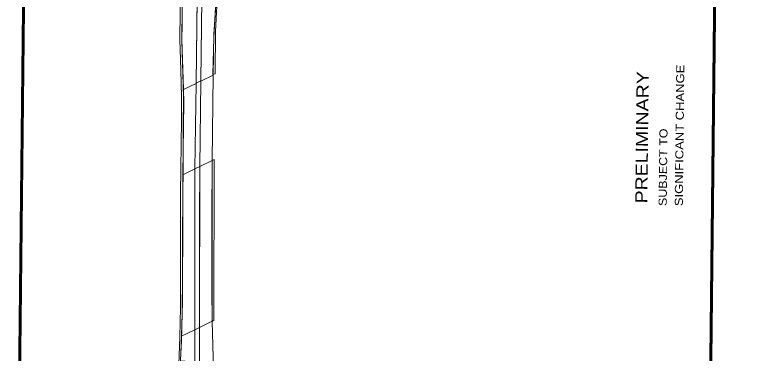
# Model space of a CAD drawing. Extents: x 2356576 to 2377878, y 6966390 to 6990634.
# Drawn here: x 2363518 to 2367164, y 6970821 to 6972488 of the extents above; entities that cross this region are included whole.
import ezdxf

# ---------------------------------------------------------------- set-up
doc = ezdxf.new("R2010")
doc.units = 0
doc.header["$LTSCALE"] = 7.1
for name, color, linetype, lineweight in [('10', 7, 'Continuous', 13), ('19', 7, 'Continuous', 13), ('8', 7, 'Continuous', 13)]:
    doc.layers.add(name, color=color, linetype=linetype, lineweight=lineweight)
doc.layers.add('5', color=7, linetype='Continuous')

msp = doc.modelspace()

# ---------------------------------------------------------------- linework, layer by layer
at = {"layer": '10'}
for points in [[(2364411.941, 6972150.306), (2364435.761, 6972161.792), (2364450.304, 6973379.724), (2364474.942, 6975290.834), (2364449.44, 6975291.283), (2364448.401, 6975249.217)], [(2364349.233, 6972119.087), (2364342.384, 6972367.508), (2364346.948, 6972816.216), (2364349.097, 6973027.453), (2364349.668, 6973070.227), (2364350.06, 6973172.738), (2364347.129, 6973327.684), (2364365.225, 6973327.282), (2364368.545, 6973567.259), (2364428.54, 6973566.551), (2364423.313, 6973123.743), (2364411.617, 6972149.404)], [(2364435.436, 6972160.979), (2364445.546, 6972973.819), (2364505.455, 6972965.741), (2364501.485, 6972629.356), (2364515.451, 6972628.365), (2364498.687, 6972392.189), (2364496.686, 6972190.744)], [(2364430.765, 6971740.43), (2364435.436, 6972160.979), (2364496.686, 6972190.744), (2364490.881, 6971769.645)], [(2364346.26, 6971699.083), (2364350.806, 6972057.614), (2364349.233, 6972119.087), (2364411.617, 6972149.404), (2364406.382, 6971728.861)], [(2364429.507, 6970948.178), (2364429.107, 6971490.067), (2364430.765, 6971740.43), (2364490.881, 6971769.645), (2364489.107, 6971490.18), (2364489.848, 6971133.24), (2364490.855, 6970978.883)], [(2364490.855, 6970978.883), (2364490.881, 6971769.645), (2364501.654, 6971775.019), (2364499.981, 6970983.653)], [(2364340.202, 6970904.333), (2364344.482, 6971073.663), (2364345.489, 6971289.033), (2364346.26, 6971699.083), (2364406.382, 6971728.861), (2364405.107, 6971490.021), (2364406.055, 6970936.781)], [(2364406.055, 6970936.781), (2364406.382, 6971728.861), (2364430.765, 6971740.43), (2364429.507, 6970948.178)], [(2364431.129, 6970286.36), (2364429.507, 6970948.178), (2364490.855, 6970978.883), (2364498.084, 6970741.164), (2364484.715, 6970735.499), (2364478.574, 6970741.704), (2364479.071, 6970428.965), (2364478.064, 6970311.844)], [(2364358.957, 6970250.395), (2364358.454, 6970781.917), (2364335.441, 6970781.971), (2364340.202, 6970904.333), (2364406.055, 6970936.781), (2364407.321, 6970275.294)]]:
    msp.add_lwpolyline(points, close=True, dxfattribs=at)
for points in [[(2364327.386, 6970637.268), (2364339.445, 6970879.671), (2364342.838, 6971017.425), (2364346.656, 6971387.289), (2364348.595, 6971939.164), (2364350.632, 6972077.051), (2364348.966, 6972142.357), (2364341.785, 6972359.904), (2364343.74, 6972447.119), (2364348.323, 6972977.027)], [(2364336.753, 6972775.328), (2364332.412, 6972366.119), (2364336.157, 6972216.275), (2364340.382, 6972084.363), (2364339.717, 6971969.415), (2364335.468, 6971607.441), (2364335.168, 6971448.659), (2364335.51, 6971156.295), (2364335.748, 6971045.371), (2364331.447, 6970900.909), (2364324.86, 6970720.364)], [(2364514.907, 6972531.91), (2364507.682, 6972405.528), (2364506.288, 6972196.078), (2364494.368, 6972193.532), (2364498.703, 6972374.898), (2364506.968, 6972523.494)]]:
    msp.add_lwpolyline(points, dxfattribs=at)
at = {"layer": '19', "lineweight": 40}
msp.add_lwpolyline([(2363758.773, 6990629.355), (2367158.576, 6990592.767), (2366922.891, 6968646.236), (2363523.088, 6968682.826)], close=True, dxfattribs=at)
at = {"layer": '8', "lineweight": 40}
for points in [[(2363753.827, 6990634.409), (2367163.63, 6990597.713), (2366927.837, 6968641.182), (2363518.034, 6968677.88)], [(2363758.773, 6990629.355), (2367158.576, 6990592.767), (2366922.891, 6968646.236), (2363523.088, 6968682.826)]]:
    msp.add_lwpolyline(points, close=True, dxfattribs=at)

# ---------------------------------------------------------------- texts
at = {"layer": '5'}
for s, height, width, p in [('SIGNIFICANT CHANGE', 39.87, 1.2, (2366811.651, 6971544.917)), ('PRELIMINARY', 59.8, 1.2, (2366636.594, 6971558.463)), ('SUBJECT TO', 39.87, 1.15, (2366732.132, 6971545.8))]:
    msp.add_text(s, height=height, rotation=89.364, dxfattribs=dict(at, width=width)).set_placement(p)

doc.saveas('drawing.dxf')
